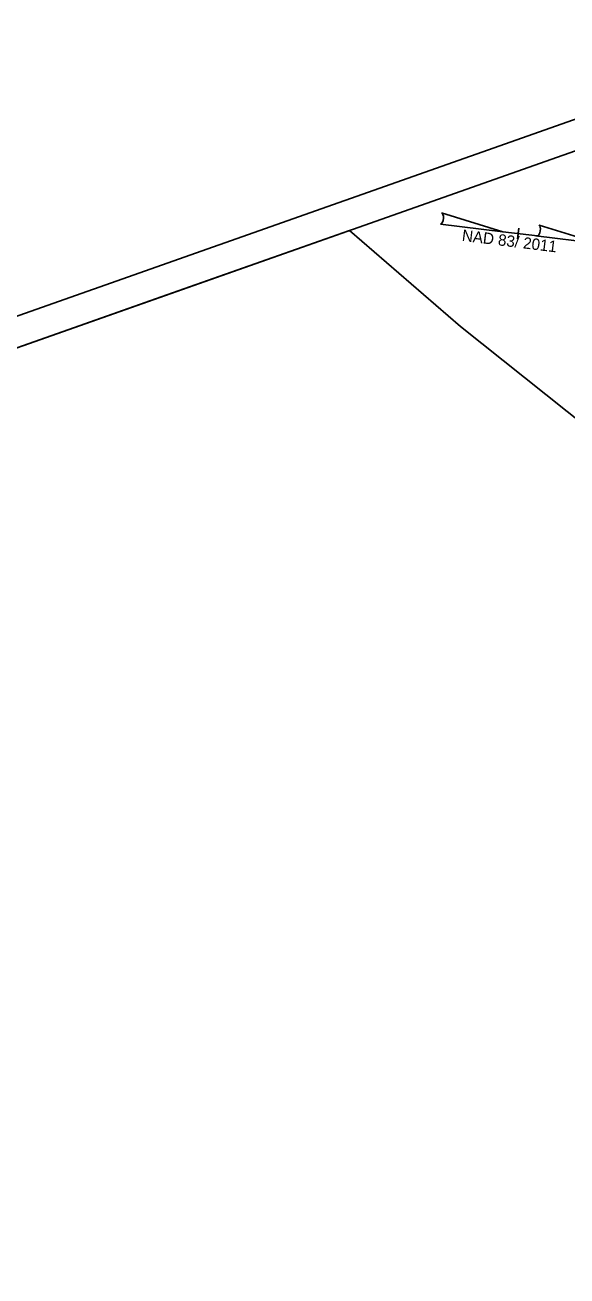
# Model space of a CAD drawing. Extents: x 473817 to 475769, y 501102 to 502694.
# Drawn here: x 474793 to 475199, y 501758 to 502694 of the extents above; entities that cross this region are included whole.
import ezdxf

# ---------------------------------------------------------------- set-up
doc = ezdxf.new("R2010")
doc.units = 0
for name, color, linetype in [('Prop North Arrow NAD83 for Plan Sheets CELL', 7, 'Continuous'), ('Sheet Clip Boundary CELL', 7, 'Continuous'), ('Sheet Plan CELL', 7, 'Continuous'), ('Sheet Plot Border Outside CELL', 7, 'Continuous')]:
    doc.layers.add(name, color=color, linetype=linetype)

msp = doc.modelspace()

# ---------------------------------------------------------------- linework, layer by layer
at = {"layer": 'Prop North Arrow NAD83 for Plan Sheets CELL'}
for p, q in [((475151.34, 502539.42), (475105.47, 502553.48)), ((475104.64, 502545.11), (475151.34, 502539.42)), ((475178.41, 502544.4), (475223.41, 502530.6)), ((475151.34, 502539.42), (475177.35, 502536.21)), ((475163.34, 502541.92), (475162.36, 502533.98)), ((475162.91, 502538.45), (475163.35, 502541.97)), ((475163.35, 502541.97), (475163.35, 502542.02)), ((475223.4, 502530.55), (475175.96, 502536.39)), ((475175.96, 502536.39), (475177.3, 502536.22))]:
    msp.add_line(p, q, dxfattribs=at)
for centre, start_param, end_param in [((475104.79, 502549.29), 0.201328, 3.141593), ((475177.41, 502540.35), 0.216388, 2.908219)]:
    msp.add_ellipse(centre, major_axis=(-0.55, -4.19), ratio=0.461098, start_param=start_param, end_param=end_param, dxfattribs=at)
at = {"layer": 'Sheet Clip Boundary CELL'}
msp.add_lwpolyline([(475119.66, 502468.38), (475036.4, 502540.29), (474903.93, 502493.58), (474817.77, 502463.2), (474310.95, 502284.49), (473981.98, 502168.49), (474331.14, 501178.25), (475584.93, 501620.34), (475533.01, 501762.61), (475513.59, 502114.66), (475441.15, 502349.5), (475422.16, 502337.99), (475311.46, 502315.79)], close=True, dxfattribs=at)
at = {"layer": 'Sheet Plan CELL'}
msp.add_lwpolyline([(475396.65, 502667.31), (473981.98, 502168.49), (474331.14, 501178.25), (475745.79, 501677.06)], close=True, dxfattribs=at)
at = {"layer": 'Sheet Plot Border Outside CELL'}
msp.add_lwpolyline([(474181.62, 501101.65), (475769.31, 501661.48), (475405.18, 502694.17), (473817.49, 502134.34)], close=True, dxfattribs=at)

# ---------------------------------------------------------------- texts
at = {"layer": 'Prop North Arrow NAD83 for Plan Sheets CELL'}
msp.add_text('NAD 83/ 2011', height=8.5, rotation=352.98225, dxfattribs=at).set_placement((475120.36, 502532.63))

doc.saveas('drawing.dxf')
